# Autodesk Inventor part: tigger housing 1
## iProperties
Created: 2006-04
Part Number: tigger housing 1
Document SubType Name: Modeling
Designer: Калинин
Author: Калинин
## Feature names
1. Выдавливание1 [Extrusion]
2. Выдавливание2 [Extrusion]
3. Выдавливание3 [Extrusion]
4. Выдавливание4 [Extrusion]
5. Сопряжение1 [Fillet]
6. Сопряжение2 [Fillet]
7. Сопряжение3 [Fillet]
8. Фаска1 [Chamfer]
9. Сопряжение4 [Fillet]
10. Отверстие1 [Hole]
11. Выдавливание5 [Extrusion]
